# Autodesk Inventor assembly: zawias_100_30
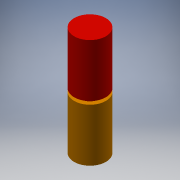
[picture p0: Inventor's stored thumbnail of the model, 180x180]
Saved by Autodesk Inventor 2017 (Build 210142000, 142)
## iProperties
Created: 2020-09
Part Number: zawias_100_30
Document SubType Name: Assembly
Designer: WindowsX
Author: WindowsX
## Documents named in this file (3)
- C:\Users\WindowsX\Desktop\brama\zawias_100_30.iam
- C:\Users\WindowsX\Desktop\brama\zawias_dolny.ipt
- C:\Users\WindowsX\Desktop\brama\zawias_gorny.ipt
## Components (2 placed, 2 different names)
1. zawias_dolny:1 — Wstaw:1
2. zawias_gorny:1 — Wstaw:1
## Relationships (1: Insert 1)
- Wstaw:1 [Insert]: zawias_dolny:1 ↔ zawias_gorny:1
